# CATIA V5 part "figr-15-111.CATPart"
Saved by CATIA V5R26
Part number: Part1
Bounding box of the stored display mesh (mm): x 0.737 to 206.429, y 0 to 112.04, z -6 to 2
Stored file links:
  D:\_Deepak\CATIA\CATIA V5 2015 Parts Files\Part files\Partfiles\c15_catia_v5_6r2015_prt\figr-15-111.CATPart
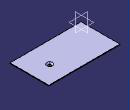
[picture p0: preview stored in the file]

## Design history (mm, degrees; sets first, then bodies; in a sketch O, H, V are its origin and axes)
SheetMetalParameters1: Thickness 2, BendRadius 4, KFactor 0.400515 {= log(min(100,max(20*SheetMetalParameters1.BendRadius,SheetMetalParameters1.Thickness)/SheetMetalParameters1.Thickness))/log(100)/2}, ReliefRadialLength 1, ReliefAxialLength 2, MinimumBendRadius 0
Body1 (main body)
  Sketch1 on xy-plane, origin (0, 0, 0), H (1, 0, 0), V (0, 1, 0)
    line L1 (0.7372, 112.0403) -> (206.4285, 112.0403)
    line L2 (206.4285, 112.0403) -> (206.4285, 0)
    line L3 (206.4285, 0) -> (0.7372, 0)
    line L4 (0.7372, 0) -> (0.7372, 112.0403)
    horizontal: L1 H, L3 H
    vertical: L2 V, L4 V
  Wall1: Thickness 2, Profile Sketch1, OffsetValue 0
  Sketch2 on face of Wall1, origin (152.409, 60.7083, 2), H (1, 0, 0), V (0, 1, 0)
    point P1 (0, 0)
  d_Stamp1: Stamp_FilletActivity true, KFacteur 0.400515 {= SheetMetalParameters1.KFactor}, NewRoot_AttribNormalisation "No Standard", Stamp_FilletRadius 2, Stamp_IntersectFilletRadius 2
